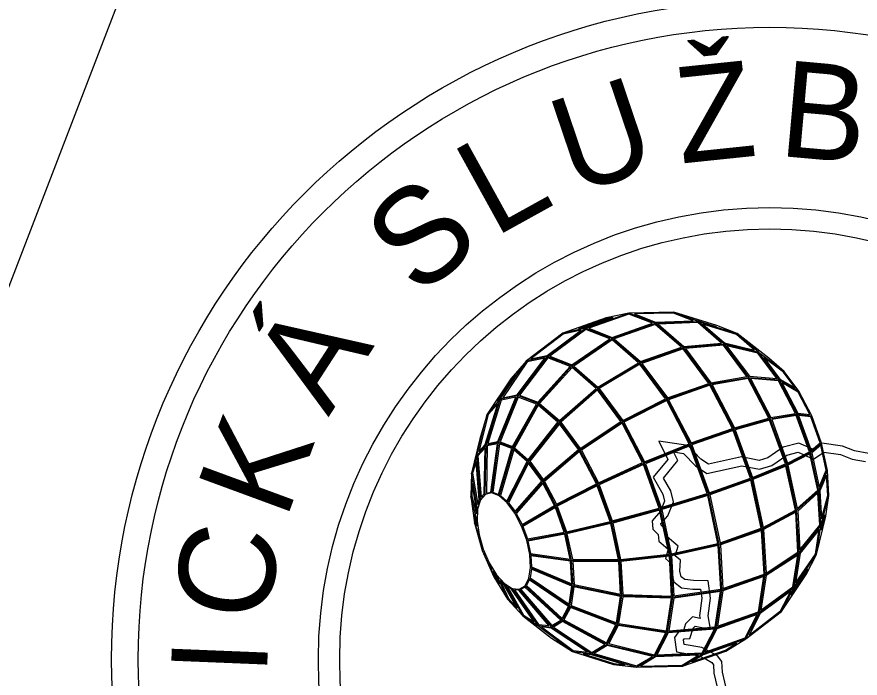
# Model space of a CAD drawing. Extents: x -755061 to -754557, y -1162352 to -1161657.
# Drawn here: x -754704.28 to -754694.4, y -1161782.82 to -1161775.08 of the extents above; entities that cross this region are included whole.
import ezdxf

# ---------------------------------------------------------------- set-up
doc = ezdxf.new("R2010")
doc.units = 0
doc.layers.add('ADJ_Formát', color=7, linetype='Continuous')

msp = doc.modelspace()

# ---------------------------------------------------------------- linework, layer by layer
at = {"layer": 'ADJ_Formát'}
for p, q in [((-754748.7218, -1161893.4678), (-754687.6626, -1161734.8116)), ((-754696.0843, -1161778.7082), (-754696.5881, -1161778.5499)), ((-754698.8832, -1161780.8432), (-754698.9546, -1161780.4239)), ((-754698.8883, -1161780.9842), (-754698.9644, -1161780.6945)), ((-754698.8658, -1161781.146), (-754698.9211, -1161781.0051)), ((-754698.8175, -1161781.3143), (-754698.8284, -1161781.3281)), ((-754698.7477, -1161781.4742), (-754698.6946, -1161781.6348)), ((-754698.6628, -1161781.6113), (-754698.5316, -1161781.898)), ((-754698.5701, -1161781.7136), (-754698.3538, -1161782.0943))]:
    msp.add_line(p, q, dxfattribs=at)
for points in [[(-754698.6946, -1161781.6348), (-754698.5316, -1161781.898), (-754698.3538, -1161782.0943), (-754698.0171, -1161782.3554), (-754697.7701, -1161782.5119), (-754697.2899, -1161782.6642), (-754697.0208, -1161782.6938), (-754696.4827, -1161782.683), (-754695.9757, -1161782.505), (-754695.7396, -1161782.3617), (-754695.3239, -1161782.0425), (-754695.0334, -1161781.6079), (-754694.9124, -1161781.3742), (-754694.8048, -1161780.926), (-754694.7684, -1161780.6848), (-754694.7853, -1161780.3909), (-754694.8541, -1161780.0705), (-754694.9686, -1161779.7521), (-754695.1187, -1161779.4639), (-754695.291, -1161779.2316), (-754695.4703, -1161779.0758), (-754695.8426, -1161778.7878), (-754696.0806, -1161778.6963), (-754696.5844, -1161778.538), (-754697.1111, -1161778.5483), (-754697.3786, -1161778.6045), (-754697.8855, -1161778.7825), (-754698.31, -1161779.1093), (-754698.4934, -1161779.3181), (-754698.77, -1161779.7318), (-754698.8569, -1161780.0205), (-754698.9546, -1161780.4239), (-754698.9644, -1161780.6945), (-754698.9211, -1161781.0051), (-754698.8284, -1161781.3281)], [(-754697.7015, -1161778.7311), (-754697.6215, -1161778.7143), (-754697.2951, -1161778.5997), (-754697.3752, -1161778.6165)], [(-754697.5819, -1161778.7269), (-754697.3062, -1161778.833), (-754696.8357, -1161778.6677), (-754697.1113, -1161778.5617)], [(-754697.0471, -1161778.5596), (-754696.7974, -1161778.6557), (-754696.359, -1161778.6382), (-754696.5866, -1161778.5506)], [(-754697.282, -1161778.851), (-754696.9756, -1161779.1175), (-754696.4957, -1161778.9489), (-754696.8022, -1161778.6825)], [(-754696.3024, -1161778.6609), (-754696.7675, -1161778.6795), (-754696.4671, -1161778.9407), (-754696.0267, -1161778.9007)], [(-754695.8488, -1161778.799), (-754696.2453, -1161778.6775), (-754695.9906, -1161778.899), (-754695.6385, -1161778.9819)], [(-754698.2591, -1161779.0858), (-754698.0695, -1161779.0461), (-754697.6713, -1161778.7503), (-754697.8802, -1161778.7941)], [(-754698.0386, -1161779.0542), (-754697.7795, -1161779.1539), (-754697.3332, -1161778.8494), (-754697.6162, -1161778.7405)], [(-754697.3074, -1161778.8621), (-754697.7574, -1161779.1692), (-754697.4749, -1161779.4148), (-754696.9995, -1161779.1298)], [(-754696.0023, -1161778.9235), (-754696.448, -1161778.964), (-754696.1504, -1161779.3653), (-754695.7286, -1161779.2925)], [(-754696.9582, -1161779.1378), (-754696.6583, -1161779.5422), (-754696.176, -1161779.3728), (-754696.4759, -1161778.9685)], [(-754695.5994, -1161779.0168), (-754695.966, -1161778.9305), (-754695.6998, -1161779.2894), (-754695.3777, -1161779.3158)], [(-754698.5897, -1161779.5398), (-754698.4206, -1161779.5043), (-754698.0946, -1161779.0769), (-754698.3026, -1161779.1205)], [(-754698.3934, -1161779.5099), (-754698.179, -1161779.5924), (-754697.7993, -1161779.1731), (-754698.06, -1161779.0728)], [(-754695.3, -1161779.2405), (-754695.5308, -1161779.0673), (-754695.3427, -1161779.3209), (-754695.1645, -1161779.4233)], [(-754697.7768, -1161779.1854), (-754698.1577, -1161779.6061), (-754697.925, -1161779.8084), (-754697.4953, -1161779.4302)], [(-754697.458, -1161779.4338), (-754697.1826, -1161779.8052), (-754696.6817, -1161779.5525), (-754696.9816, -1161779.1482)], [(-754698.654, -1161779.5808), (-754698.6275, -1161779.5507), (-754698.4379, -1161779.2738), (-754698.4834, -1161779.3257)], [(-754695.7134, -1161779.3152), (-754696.1369, -1161779.3884), (-754695.8747, -1161779.8918), (-754695.4722, -1161779.7784)], [(-754695.3591, -1161779.3424), (-754695.685, -1161779.3157), (-754695.4471, -1161779.7724), (-754695.1604, -1161779.7239)], [(-754696.6451, -1161779.564), (-754696.382, -1161780.0692), (-754695.8988, -1161779.8996), (-754696.1619, -1161779.3944)], [(-754695.3204, -1161779.3626), (-754695.1334, -1161779.7216), (-754694.9905, -1161779.7372), (-754695.1281, -1161779.473)], [(-754697.4782, -1161779.4485), (-754697.9081, -1161779.8268), (-754697.6811, -1161780.1328), (-754697.2043, -1161779.8179)], [(-754698.8676, -1161780.1703), (-754698.7946, -1161780.0871), (-754698.6469, -1161779.6107), (-754698.7586, -1161779.7378)], [(-754698.7652, -1161780.0768), (-754698.6464, -1161780.0518), (-754698.4339, -1161779.5326), (-754698.6079, -1161779.5691)], [(-754698.621, -1161780.0556), (-754698.4728, -1161780.1127), (-754698.1934, -1161779.6136), (-754698.4065, -1161779.5316)], [(-754697.1694, -1161779.8265), (-754696.928, -1161780.2901), (-754696.4055, -1161780.0782), (-754696.6682, -1161779.5737)], [(-754698.1721, -1161779.6266), (-754698.4513, -1161780.1255), (-754698.2896, -1161780.266), (-754697.9422, -1161779.8266)], [(-754695.4618, -1161779.8014), (-754695.8648, -1161779.915), (-754695.664, -1161780.4731), (-754695.2771, -1161780.3149)], [(-754695.1496, -1161779.7474), (-754695.4372, -1161779.7961), (-754695.2543, -1161780.3044), (-754694.9968, -1161780.1723)], [(-754694.9778, -1161779.7637), (-754695.1229, -1161779.7479), (-754694.9756, -1161780.1572), (-754694.8688, -1161780.0666)], [(-754697.9253, -1161779.8455), (-754698.2722, -1161780.2843), (-754698.1135, -1161780.4982), (-754697.7011, -1161780.1478)], [(-754697.1911, -1161779.8391), (-754697.6678, -1161780.154), (-754697.4687, -1161780.5363), (-754696.951, -1161780.3)], [(-754696.372, -1161780.0923), (-754696.1708, -1161780.6517), (-754695.6874, -1161780.4819), (-754695.8886, -1161779.9225)], [(-754698.7812, -1161780.6555), (-754698.7291, -1161780.6445), (-754698.6521, -1161780.0786), (-754698.7711, -1161780.1036)], [(-754698.6271, -1161780.0801), (-754698.7042, -1161780.6468), (-754698.6374, -1161780.6725), (-754698.4823, -1161780.1358)], [(-754696.3954, -1161780.1011), (-754696.918, -1161780.313), (-754696.7334, -1161780.8262), (-754696.1946, -1161780.6595)], [(-754694.862, -1161780.0936), (-754694.9675, -1161780.1831), (-754694.8812, -1161780.585), (-754694.7984, -1161780.3897)], [(-754698.8795, -1161780.2217), (-754698.8407, -1161780.7051), (-754698.8064, -1161780.6661), (-754698.7966, -1161780.1273)], [(-754698.4606, -1161780.1505), (-754698.615, -1161780.6849), (-754698.5397, -1161780.7504), (-754698.3035, -1161780.2871)], [(-754697.6879, -1161780.1694), (-754698.0999, -1161780.5195), (-754697.9602, -1161780.7878), (-754697.4912, -1161780.5472)], [(-754694.9901, -1161780.197), (-754695.2471, -1161780.3287), (-754695.1379, -1161780.8372), (-754694.8989, -1161780.6218)], [(-754698.8798, -1161780.7886), (-754698.8635, -1161780.7342), (-754698.8996, -1161780.2846), (-754698.9418, -1161780.4247)], [(-754698.2859, -1161780.3077), (-754698.5211, -1161780.7691), (-754698.4452, -1161780.8715), (-754698.1317, -1161780.5157)], [(-754696.941, -1161780.323), (-754697.4586, -1161780.5592), (-754697.3063, -1161780.9826), (-754696.7575, -1161780.8332)], [(-754695.2704, -1161780.3392), (-754695.657, -1161780.4972), (-754695.5367, -1161781.0572), (-754695.1598, -1161780.8544)], [(-754695.6806, -1161780.5061), (-754696.1638, -1161780.6757), (-754696.0432, -1161781.2376), (-754695.56, -1161781.0679)], [(-754694.7947, -1161780.4451), (-754694.8725, -1161780.6284), (-754694.8535, -1161780.9579), (-754694.781, -1161780.6835)], [(-754698.8978, -1161780.8991), (-754698.8957, -1161780.844), (-754698.9465, -1161780.5458), (-754698.9519, -1161780.6931)], [(-754698.1183, -1161780.5383), (-754698.431, -1161780.8932), (-754698.3628, -1161781.0241), (-754697.9821, -1161780.7998)], [(-754697.4812, -1161780.5702), (-754697.95, -1161780.8107), (-754697.843, -1161781.1083), (-754697.3307, -1161780.9887)], [(-754698.2723, -1161781.3744), (-754698.3081, -1161781.2075), (-754698.3678, -1161781.0415), (-754698.446, -1161780.8914), (-754698.5358, -1161780.7703), (-754698.6292, -1161780.6891), (-754698.7179, -1161780.6549), (-754698.794, -1161780.6709), (-754698.8508, -1161780.7356), (-754698.8832, -1161780.8432), (-754698.8883, -1161780.9842), (-754698.8658, -1161781.146), (-754698.8175, -1161781.3143), (-754698.7477, -1161781.4742), (-754698.6628, -1161781.6113), (-754698.5701, -1161781.7136), (-754698.4781, -1161781.7719), (-754698.3947, -1161781.7811), (-754698.3275, -1161781.7403), (-754698.2824, -1161781.6532), (-754698.2634, -1161781.5275)], [(-754696.1877, -1161780.6836), (-754696.7265, -1161780.8502), (-754696.6158, -1161781.3658), (-754696.0673, -1161781.2446)], [(-754694.8961, -1161780.653), (-754695.1327, -1161780.8663), (-754695.1065, -1161781.3222), (-754694.8742, -1161781.0329)], [(-754698.9089, -1161781.0019), (-754698.8927, -1161781.0431), (-754698.9006, -1161780.9866), (-754698.9229, -1161780.9019)], [(-754697.9722, -1161780.823), (-754698.3525, -1161781.047), (-754698.2999, -1161781.1932), (-754697.8677, -1161781.1134)], [(-754696.7506, -1161780.8572), (-754697.2995, -1161781.0067), (-754697.2082, -1161781.4319), (-754696.6406, -1161781.3698)], [(-754695.1569, -1161780.8813), (-754695.5325, -1161781.0833), (-754695.5032, -1161781.5918), (-754695.13, -1161781.3489)], [(-754694.8151, -1161780.9105), (-754694.8492, -1161781.0396), (-754694.8565, -1161781.0878), (-754694.8171, -1161780.9236)], [(-754697.3237, -1161781.0128), (-754697.8362, -1161781.1324), (-754697.7721, -1161781.4309), (-754697.2335, -1161781.433)], [(-754695.557, -1161781.0934), (-754696.0394, -1161781.2628), (-754696.0099, -1161781.7748), (-754695.5275, -1161781.6054)], [(-754694.8808, -1161781.081), (-754695.1052, -1161781.3606), (-754695.1579, -1161781.7094), (-754694.9243, -1161781.3695)], [(-754698.2932, -1161781.2174), (-754698.2619, -1161781.3632), (-754697.7982, -1161781.4285), (-754697.8607, -1161781.1375)], [(-754696.0641, -1161781.2695), (-754696.6123, -1161781.3906), (-754696.5852, -1161781.8608), (-754696.0346, -1161781.7814)], [(-754698.8192, -1161781.3148), (-754698.8231, -1161781.3013)], [(-754698.805, -1161781.3505), (-754698.7917, -1161781.3809)], [(-754698.2589, -1161781.3889), (-754698.2514, -1161781.519), (-754697.7789, -1161781.7179), (-754697.7941, -1161781.4543)], [(-754696.6372, -1161781.3946), (-754697.2049, -1161781.4567), (-754697.1825, -1161781.8442), (-754696.6102, -1161781.8622)], [(-754695.1336, -1161781.3811), (-754695.5029, -1161781.6215), (-754695.5643, -1161782.0279), (-754695.1899, -1161781.7542)], [(-754697.2298, -1161781.458), (-754697.769, -1161781.4559), (-754697.7533, -1161781.7269), (-754697.2078, -1161781.8407)], [(-754698.6258, -1161781.7221), (-754698.6738, -1161781.6172), (-754698.7026, -1161781.5707), (-754698.6832, -1161781.6295)], [(-754697.7791, -1161781.745), (-754698.2535, -1161781.5453), (-754698.2689, -1161781.6473), (-754697.8111, -1161781.957)], [(-754695.0158, -1161781.5468), (-754695.1676, -1161781.7677), (-754695.21, -1161781.8495), (-754695.0441, -1161781.6015)], [(-754698.4208, -1161782.0017), (-754698.5803, -1161781.721), (-754698.6178, -1161781.6796), (-754698.521, -1161781.891)], [(-754698.2778, -1161781.6715), (-754698.312, -1161781.7376), (-754697.8918, -1161782.1253), (-754697.8179, -1161781.9826)], [(-754695.5299, -1161781.6328), (-754696.0102, -1161781.8014), (-754696.0726, -1161782.2151), (-754695.5924, -1161782.0464)], [(-754698.2225, -1161782.1627), (-754698.4869, -1161781.7811), (-754698.5345, -1161781.7509), (-754698.3445, -1161782.0854)], [(-754698.0472, -1161782.208), (-754698.401, -1161781.793), (-754698.4522, -1161781.7874), (-754698.1701, -1161782.1944)], [(-754697.9089, -1161782.1435), (-754698.3291, -1161781.7559), (-754698.3757, -1161781.7842), (-754698.0146, -1161782.2076)], [(-754697.7549, -1161781.7522), (-754697.7878, -1161781.9704), (-754697.2553, -1161782.1762), (-754697.2085, -1161781.8661)], [(-754696.6114, -1161781.8872), (-754697.1836, -1161781.8691), (-754697.231, -1161782.183), (-754696.6687, -1161782.2667)], [(-754696.0363, -1161781.8069), (-754696.586, -1161781.8861), (-754696.6435, -1161782.2672), (-754696.099, -1161782.2221)], [(-754695.2139, -1161781.8027), (-754695.5714, -1161782.0641), (-754695.7026, -1161782.3176), (-754695.3338, -1161782.0343)], [(-754697.2628, -1161782.2001), (-754697.7957, -1161781.9941), (-754697.8715, -1161782.1404), (-754697.3715, -1161782.4101)], [(-754695.6067, -1161782.0779), (-754696.0793, -1161782.2439), (-754696.221, -1161782.5175), (-754695.7484, -1161782.3516)], [(-754697.3914, -1161782.4278), (-754697.8879, -1161782.16), (-754697.9939, -1161782.2243), (-754697.5462, -1161782.5217)], [(-754697.5963, -1161782.5185), (-754698.0216, -1161782.2359), (-754698.1331, -1161782.2236), (-754697.7653, -1161782.4998)], [(-754696.6774, -1161782.2907), (-754697.2383, -1161782.2072), (-754697.3478, -1161782.4187), (-754696.8104, -1161782.5477)], [(-754696.1096, -1161782.2481), (-754696.6503, -1161782.2928), (-754696.7828, -1161782.5488), (-754696.2543, -1161782.5276)], [(-754696.8363, -1161782.5672), (-754697.3641, -1161782.4405), (-754697.516, -1161782.5326), (-754697.0225, -1161782.6803)], [(-754695.8487, -1161782.4133), (-754696.2412, -1161782.5511), (-754696.3736, -1161782.6315), (-754695.981, -1161782.4936)], [(-754697.1564, -1161782.6663), (-754697.549, -1161782.5488), (-754697.6459, -1161782.5381), (-754697.2873, -1161782.6519)], [(-754696.2944, -1161782.5542), (-754696.8001, -1161782.5745), (-754696.9746, -1161782.6804), (-754696.4863, -1161782.6706)]]:
    msp.add_lwpolyline(points, close=True, dxfattribs=at)
for points in [[(-754698.7179, -1161780.6549), (-754698.6374, -1161780.0627), (-754698.4134, -1161779.5155), (-754698.0642, -1161779.0577), (-754697.6181, -1161778.7264), (-754697.1111, -1161778.5483)], [(-754695.7396, -1161782.3617), (-754695.5811, -1161782.0557), (-754695.5144, -1161781.6141), (-754695.5455, -1161781.0761), (-754695.6714, -1161780.4896), (-754695.8811, -1161779.9066), (-754696.1558, -1161779.379), (-754696.4713, -1161778.9536), (-754696.7995, -1161778.6683), (-754697.1111, -1161778.5483)], [(-754695.3239, -1161782.0425), (-754695.1783, -1161781.7612), (-754695.1171, -1161781.3554), (-754695.1456, -1161780.861), (-754695.2613, -1161780.322), (-754695.454, -1161779.7862), (-754695.7065, -1161779.3014), (-754695.9964, -1161778.9105), (-754696.298, -1161778.6482), (-754696.5844, -1161778.538)], [(-754698.6292, -1161780.6891), (-754698.4671, -1161780.1282), (-754698.1755, -1161779.6071), (-754697.7779, -1161779.168), (-754697.3064, -1161778.8463), (-754696.7995, -1161778.6683), (-754696.298, -1161778.6482), (-754695.8426, -1161778.7878)], [(-754696.4827, -1161782.683), (-754696.2465, -1161782.5398), (-754696.0881, -1161782.2337), (-754696.0214, -1161781.7921), (-754696.0524, -1161781.2541), (-754696.1784, -1161780.6676), (-754696.388, -1161780.0846), (-754696.6628, -1161779.557), (-754696.9783, -1161779.1317), (-754697.3064, -1161778.8463), (-754697.6181, -1161778.7264), (-754697.8855, -1161778.7825)], [(-754694.9124, -1161781.3742), (-754694.8615, -1161781.037), (-754694.8852, -1161780.6263), (-754694.9813, -1161780.1784), (-754695.1414, -1161779.7333), (-754695.3512, -1161779.3305), (-754695.5921, -1161779.0057), (-754695.8426, -1161778.7878)], [(-754698.5358, -1161780.7703), (-754698.2879, -1161780.2841), (-754697.9249, -1161779.825), (-754697.4763, -1161779.4302), (-754696.9783, -1161779.1317), (-754696.4713, -1161778.9536), (-754695.9964, -1161778.9105), (-754695.5921, -1161779.0057), (-754695.291, -1161779.2316)], [(-754698.794, -1161780.6709), (-754698.7835, -1161780.0934), (-754698.6176, -1161779.5584), (-754698.31, -1161779.1093)], [(-754697.0208, -1161782.6938), (-754696.8038, -1161782.5622), (-754696.6582, -1161782.2809), (-754696.5969, -1161781.8751), (-754696.6254, -1161781.3807), (-754696.7412, -1161780.8417), (-754696.9339, -1161780.3059), (-754697.1864, -1161779.8211), (-754697.4763, -1161779.4302), (-754697.7779, -1161779.168), (-754698.0642, -1161779.0577), (-754698.31, -1161779.1093)], [(-754698.446, -1161780.8914), (-754698.1156, -1161780.5164), (-754697.6841, -1161780.1498), (-754697.1864, -1161779.8211), (-754696.6628, -1161779.557), (-754696.1558, -1161779.379), (-754695.7065, -1161779.3014), (-754695.3512, -1161779.3305), (-754695.1187, -1161779.4639)], [(-754697.7701, -1161782.5119), (-754697.5465, -1161782.5365), (-754697.3662, -1161782.4271), (-754697.2453, -1161782.1935), (-754697.1943, -1161781.8563), (-754697.218, -1161781.4455), (-754697.3142, -1161780.9977), (-754697.4743, -1161780.5526), (-754697.6841, -1161780.1498), (-754697.9249, -1161779.825), (-754698.1755, -1161779.6071), (-754698.4134, -1161779.5155), (-754698.6176, -1161779.5584), (-754698.77, -1161779.7318)], [(-754698.8508, -1161780.7356), (-754698.8924, -1161780.2175), (-754698.77, -1161779.7318)], [(-754698.3678, -1161781.0415), (-754697.9655, -1161780.8046), (-754697.4743, -1161780.5526), (-754696.9339, -1161780.3059), (-754696.388, -1161780.0846), (-754695.8811, -1161779.9066), (-754695.454, -1161779.7862), (-754695.1414, -1161779.7333), (-754694.9686, -1161779.7521)], [(-754698.3538, -1161782.0943), (-754698.1771, -1161782.2062), (-754698.0172, -1161782.2238), (-754697.8882, -1161782.1456), (-754697.8017, -1161781.9784), (-754697.7653, -1161781.7372), (-754697.7822, -1161781.4434), (-754697.851, -1161781.123), (-754697.9655, -1161780.8046), (-754698.1156, -1161780.5164), (-754698.2879, -1161780.2841), (-754698.4671, -1161780.1282), (-754698.6374, -1161780.0627), (-754698.7835, -1161780.0934), (-754698.8924, -1161780.2175), (-754698.9546, -1161780.4239)], [(-754698.3081, -1161781.2075), (-754697.851, -1161781.123), (-754697.3142, -1161780.9977), (-754696.7412, -1161780.8417), (-754696.1784, -1161780.6676), (-754695.6714, -1161780.4896), (-754695.2613, -1161780.322), (-754694.9813, -1161780.1784), (-754694.8541, -1161780.0705)], [(-754694.2983, -1161780.1911), (-754694.469, -1161780.1609), (-754694.6079, -1161780.1077), (-754694.8509, -1161780.0703), (-754694.9571, -1161780.1437), (-754695.1214, -1161780.0714), (-754695.3016, -1161780.1194), (-754695.4816, -1161780.2424), (-754695.5842, -1161780.2737), (-754695.7903, -1161780.2334), (-754696.1788, -1161780.3185), (-754696.2667, -1161780.26), (-754696.4213, -1161780.0977), (-754696.7601, -1161780.0487), (-754696.6564, -1161780.2621), (-754696.8285, -1161780.4695), (-754696.714, -1161780.6678), (-754696.6921, -1161780.7519), (-754696.7393, -1161780.8673), (-754696.8382, -1161780.98), (-754696.8311, -1161781.0783), (-754696.7668, -1161781.1407), (-754696.761, -1161781.2202), (-754696.6493, -1161781.3112), (-754696.6834, -1161781.4223), (-754696.6109, -1161781.4858), (-754696.617, -1161781.5806), (-754696.5862, -1161781.6966), (-754696.4943, -1161781.764), (-754696.3612, -1161781.7806), (-754696.2703, -1161781.7821), (-754696.2549, -1161781.8863), (-754696.2823, -1161782.0942), (-754696.2777, -1161782.1227), (-754696.3672, -1161782.1054), (-754696.4466, -1161782.1859), (-754696.471, -1161782.2632), (-754696.5174, -1161782.2656), (-754696.576, -1161782.347), (-754696.5524, -1161782.5162), (-754696.288, -1161782.5612), (-754696.2072, -1161782.6019), (-754696.139, -1161782.6405), (-754696.1193, -1161782.6656), (-754696.1143, -1161782.7657), (-754696.0571, -1161783.011)], [(-754696.021, -1161782.6287), (-754696.0726, -1161782.5632), (-754696.16, -1161782.5136), (-754696.2564, -1161782.4652), (-754696.4635, -1161782.4299), (-754696.4714, -1161782.3729), (-754696.4643, -1161782.363), (-754696.3966, -1161782.3595), (-754696.3585, -1161782.239), (-754696.3336, -1161782.2138), (-754696.156, -1161782.2481), (-754696.1813, -1161782.0927), (-754696.1539, -1161781.8855), (-754696.1838, -1161781.6835), (-754696.3542, -1161781.6807), (-754696.4561, -1161781.668), (-754696.4986, -1161781.6368), (-754696.5161, -1161781.5707), (-754696.5079, -1161781.443), (-754696.5688, -1161781.3897), (-754696.534, -1161781.2762), (-754696.6644, -1161781.1699), (-754696.6699, -1161781.0954), (-754696.7341, -1161781.0331), (-754696.7355, -1161781.0146), (-754696.653, -1161780.9207), (-754696.587, -1161780.759), (-754696.6206, -1161780.6295), (-754696.7071, -1161780.4798), (-754696.5383, -1161780.2764), (-754696.5877, -1161780.1747), (-754696.4698, -1161780.1917), (-754696.3314, -1161780.3371), (-754696.1989, -1161780.4253), (-754695.7891, -1161780.3356), (-754695.5789, -1161780.3766), (-754695.4379, -1161780.3336), (-754695.2593, -1161780.2116), (-754695.1296, -1161780.177), (-754694.9463, -1161780.2577), (-754694.8268, -1161780.1752), (-754694.6337, -1161780.2049), (-754694.4959, -1161780.2577), (-754694.3397, -1161780.2854)], [(-754698.2723, -1161781.3744), (-754697.7822, -1161781.4434), (-754697.218, -1161781.4455), (-754696.6254, -1161781.3807), (-754696.0524, -1161781.2541), (-754695.5455, -1161781.0761), (-754695.1456, -1161780.861), (-754694.8852, -1161780.6263), (-754694.7853, -1161780.3909)], [(-754698.2634, -1161781.5275), (-754697.7653, -1161781.7372), (-754697.1943, -1161781.8563), (-754696.5969, -1161781.8751), (-754696.0214, -1161781.7921), (-754695.5144, -1161781.6141), (-754695.1171, -1161781.3554), (-754694.8615, -1161781.037), (-754694.7684, -1161780.6848)], [(-754698.2824, -1161781.6532), (-754697.8017, -1161781.9784), (-754697.2453, -1161782.1935), (-754696.6582, -1161782.2809), (-754696.0881, -1161782.2337), (-754695.5811, -1161782.0557), (-754695.1783, -1161781.7612), (-754694.9124, -1161781.3742)], [(-754698.4781, -1161781.7719), (-754698.1771, -1161782.2062), (-754697.7701, -1161782.5119)], [(-754698.3947, -1161781.7811), (-754698.0172, -1161782.2238), (-754697.5465, -1161782.5365), (-754697.0208, -1161782.6938)], [(-754698.3275, -1161781.7403), (-754697.8882, -1161782.1456), (-754697.3662, -1161782.4271), (-754696.8038, -1161782.5622), (-754696.2465, -1161782.5398), (-754695.7396, -1161782.3617)], [(-754695.96, -1161782.9871), (-754696.0149, -1161782.7518), (-754696.021, -1161782.6287)]]:
    msp.add_lwpolyline(points, dxfattribs=at)
for centre, radius in [((-754695.4601, -1161782.6033), 7.7125), ((-754695.4601, -1161782.6033), 7.4), ((-754695.4601, -1161782.6033), 7.4), ((-754695.4601, -1161782.6034), 5.2894), ((-754695.4601, -1161782.6033), 5.2894), ((-754695.4601, -1161782.6034), 5.0394)]:
    msp.add_circle(centre, radius, dxfattribs=at)
msp.add_arc((-754695.4601, -1161782.6033), 5.0394, 261.0755, 38.88248, dxfattribs=at)

# ---------------------------------------------------------------- texts
for s, rotation, p in [('Ž', 5.95449, (-754696.5052, -1161776.7998)), ('B', 354.88809, (-754695.3718, -1161776.7071)), ('U', 18.71936, (-754697.7617, -1161777.1741)), ('L', 28.9418, (-754698.6887, -1161777.6688)), ('S', 40.0082, (-754699.5758, -1161778.3802)), ('Á', 57.03505, (-754700.632, -1161779.7705)), ('K', 69.79992, (-754701.1301, -1161780.9833)), ('C', 81.72083, (-754701.3425, -1161782.1894)), ('I', 87.68128, (-754701.3536, -1161782.8025))]:
    msp.add_text(s, height=1.125, rotation=rotation, dxfattribs=at).set_placement(p)

doc.saveas('drawing.dxf')
